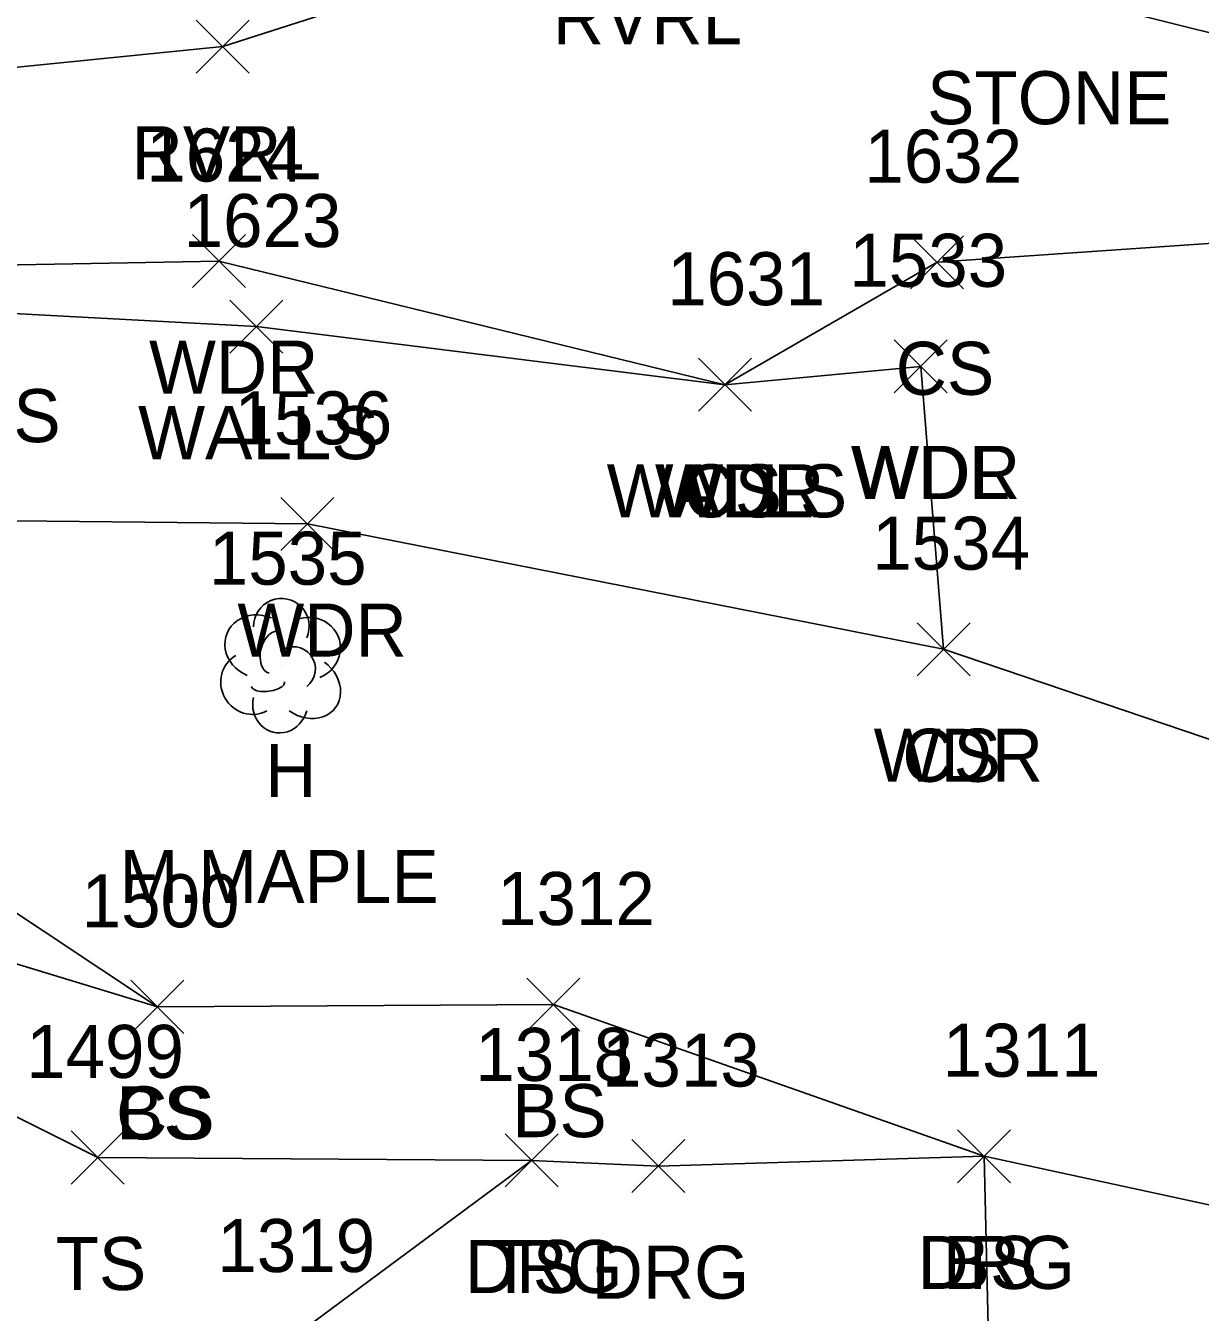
# Model space of a CAD drawing. Extents: x 1537342 to 1542195, y 163002 to 168596.
# Drawn here: x 1541894.54 to 1541938.81, y 163290.52 to 163339.03 of the extents above; entities that cross this region are included whole.
import ezdxf

# ---------------------------------------------------------------- set-up
doc = ezdxf.new("R2010")
doc.units = 0
for name, color, linetype in [('L_A', 7, 'Continuous'), ('L_C', 7, 'Continuous'), ('L_I', 7, 'Continuous'), ('L_TIC', 7, 'Continuous'), ('LASF', 7, 'Continuous'), ('LAWA', 7, 'Continuous'), ('LAWE', 7, 'Continuous'), ('LELB', 7, 'Continuous'), ('LTD', 7, 'Continuous'), ('LWS', 7, 'Continuous'), ('R_A', 7, 'Continuous'), ('R_I', 7, 'Continuous'), ('R_TIC', 7, 'Continuous'), ('RDG', 7, 'Continuous')]:
    doc.layers.add(name, color=color, linetype=linetype)

msp = doc.modelspace()

# ---------------------------------------------------------------- linework, layer by layer
at = {"layer": 'L_TIC'}
for points in [[(1541900.965, 163337.242), (1541902.965, 163339.242)], [(1541902.965, 163337.242), (1541900.965, 163339.242)], [(1541900.823, 163329.154), (1541902.823, 163331.154)], [(1541902.823, 163329.154), (1541900.823, 163331.154)], [(1541927.892, 163329.111), (1541929.892, 163331.111)], [(1541929.892, 163329.111), (1541927.892, 163331.111)], [(1541902.232, 163326.684), (1541904.232, 163328.684)], [(1541904.232, 163326.684), (1541902.232, 163328.684)], [(1541927.278, 163325.185), (1541929.278, 163327.185)], [(1541929.278, 163325.185), (1541927.278, 163327.185)], [(1541927.278, 163325.185), (1541929.278, 163327.185)], [(1541929.278, 163325.185), (1541927.278, 163327.185)], [(1541919.894, 163324.491), (1541921.894, 163326.491)], [(1541921.894, 163324.491), (1541919.894, 163326.491)], [(1541919.894, 163324.491), (1541921.894, 163326.491)], [(1541921.894, 163324.491), (1541919.894, 163326.491)], [(1541919.894, 163324.491), (1541921.894, 163326.491)], [(1541921.894, 163324.491), (1541919.894, 163326.491)], [(1541919.894, 163324.491), (1541921.894, 163326.491)], [(1541921.894, 163324.491), (1541919.894, 163326.491)], [(1541904.155, 163319.242), (1541906.155, 163321.242)], [(1541906.155, 163319.242), (1541904.155, 163321.242)], [(1541928.141, 163314.519), (1541930.141, 163316.519)], [(1541930.141, 163314.519), (1541928.141, 163316.519)], [(1541928.141, 163314.519), (1541930.141, 163316.519)], [(1541930.141, 163314.519), (1541928.141, 163316.519)], [(1541913.432, 163301.118), (1541915.432, 163303.118)], [(1541915.432, 163301.118), (1541913.432, 163303.118)], [(1541898.504, 163301.033), (1541900.504, 163303.033)], [(1541900.504, 163301.033), (1541898.504, 163303.033)], [(1541898.504, 163301.033), (1541900.504, 163303.033)], [(1541900.504, 163301.033), (1541898.504, 163303.033)], [(1541896.255, 163295.352), (1541898.255, 163297.352)], [(1541898.255, 163295.352), (1541896.255, 163297.352)], [(1541929.665, 163295.396), (1541931.665, 163297.396)], [(1541931.665, 163295.396), (1541929.665, 163297.396)], [(1541912.61, 163295.24), (1541914.61, 163297.24)], [(1541914.61, 163295.24), (1541912.61, 163297.24)]]:
    msp.add_lwpolyline(points, dxfattribs=at)
at = {"layer": 'LASF'}
msp.add_lwpolyline([(1541995.881, 163321.623), (1541975.609, 163331.573), (1541964.354, 163336.559), (1541946.913, 163336.834), (1541932.973, 163340.315), (1541930.286, 163345.761)], dxfattribs=at)
at = {"layer": 'LAWA'}
for points in [[(1541928.278, 163326.185), (1541929.141, 163315.519), (1541905.155, 163320.242), (1541889.19, 163320.415), (1541870.486, 163327.732), (1541854.509, 163332.258), (1541871.283, 163331.328), (1541890.104, 163329.934), (1541901.823, 163330.154), (1541920.894, 163325.491)], [(1541928.278, 163326.185), (1541920.894, 163325.491)]]:
    msp.add_lwpolyline(points, dxfattribs=at)
at = {"layer": 'LAWE'}
msp.add_lwpolyline([(1541842.538, 163329.294), (1541847.215, 163332.13), (1541859.961, 163336.541), (1541870.001, 163336.588), (1541887.847, 163336.83), (1541901.965, 163338.242), (1541917.838, 163343.333), (1541930.286, 163345.761), (1541946.347, 163346.77), (1541962.456, 163344.962)], dxfattribs=at)
at = {"layer": 'LELB'}
for points in [[(1541920.894, 163325.491), (1541928.892, 163330.111), (1541946.235, 163331.307), (1541955.972, 163331.056), (1541975.609, 163331.573)], [(1541913.61, 163296.24), (1541897.255, 163296.352), (1541879.102, 163305.411), (1541865.415, 163313.569), (1541849.959, 163321.033), (1541836.165, 163327.361)], [(1541899.504, 163302.033), (1541880.926, 163307.684), (1541867.753, 163316.599), (1541851.251, 163322.573), (1541842.419, 163327.722)], [(1542002.438, 163218.438), (1541992.576, 163218.503), (1541981.665, 163227.078), (1541972.727, 163235.185), (1541952.245, 163252.94), (1541934.224, 163270.875), (1541926.758, 163276.805), (1541931.045, 163280.387), (1541930.665, 163296.396), (1541914.432, 163302.118), (1541899.504, 163302.033), (1541884.497, 163311.998), (1541872.596, 163319.595), (1541857.311, 163324.696)], [(1541972.352, 163296.503), (1541957.804, 163303.546), (1541943.486, 163310.651), (1541929.141, 163315.519)]]:
    msp.add_lwpolyline(points, dxfattribs=at)
at = {"layer": 'LTD'}
msp.add_line((1541904.131, 163314.95), (1541904.131, 163314.95), dxfattribs=at)
msp.add_line((1541904.131, 163314.95), (1541904.131, 163314.95), dxfattribs=at)
msp.add_arc((1541904.178, 163316.384), 1.047, 335.5272, 180.9563, dxfattribs=at)
for centre, major_axis, ratio, start_param, end_param in [((1541903.339, 163315.616), (1.21, -0.512), 0.895232, 1.570796, 4.712389), ((1541905.173, 163315.533), (-1.141, -0.483), 0.949671, 1.570796, 4.712389), ((1541903.923, 163315.408), (-0.208, -0.792), 0.645439, 3.141593, 6.283185), ((1541904.631, 163314.783), (-0.5, 0.667), 0.989748, 3.141593, 6.283185), ((1541903.048, 163314.241), (0.584, -1.042), 0.959034, 3.141593, 6.283185), ((1541905.131, 163314.117), (-1.09, 0.792), 0.841452, 1.570796, 4.712389), ((1541903.673, 163314.2), (-0.625, -0.083), 0.423636, 0, 3.141593), ((1541904.131, 163313.45), (0.265, 1.061), 0.942809, 1.570796, 4.712389)]:
    msp.add_ellipse(centre, major_axis=major_axis, ratio=ratio, start_param=start_param, end_param=end_param, dxfattribs=at)
at = {"layer": 'LWS'}
msp.add_lwpolyline([(1541857.311, 163324.696), (1541870.486, 163327.732), (1541886.38, 163327.11), (1541891.246, 163328.326), (1541903.232, 163327.684), (1541920.894, 163325.491)], dxfattribs=at)
at = {"layer": 'R_TIC'}
for points in [[(1541929.665, 163295.396), (1541931.665, 163297.396)], [(1541931.665, 163295.396), (1541929.665, 163297.396)], [(1541912.61, 163295.24), (1541914.61, 163297.24)], [(1541914.61, 163295.24), (1541912.61, 163297.24)], [(1541917.384, 163295.027), (1541919.384, 163297.027)], [(1541919.384, 163295.027), (1541917.384, 163297.027)]]:
    msp.add_lwpolyline(points, dxfattribs=at)
at = {"layer": 'RDG'}
msp.add_lwpolyline([(1542017.62, 163206.917), (1542015.196, 163226.11), (1542009.877, 163243.692), (1541994.503, 163258.921), (1541988.515, 163265.136), (1541982.386, 163272.123), (1541977.907, 163278.251), (1541973.34, 163281.582), (1541963.148, 163285.487), (1541948.659, 163292.511), (1541930.665, 163296.396), (1541918.384, 163296.027), (1541913.61, 163296.24), (1541903.895, 163289.032)], dxfattribs=at)

# ---------------------------------------------------------------- texts
at = {"layer": 'L_A'}
for s, p in [('RVRL', (1541914.405, 163338.333)), ('STONE', (1541928.516, 163335.315)), ('RVRL', (1541898.532, 163333.242)), ('WDR', (1541899.185, 163325.154)), ('CS', (1541927.333, 163325.111)), ('WALLS', (1541886.789, 163323.326)), ('WALLS', (1541898.776, 163322.684)), ('WDR', (1541925.641, 163321.185)), ('WDL', (1541925.696, 163321.185)), ('WALLS', (1541916.437, 163320.491)), ('CS', (1541919.335, 163320.491)), ('WDR', (1541918.256, 163320.491)), ('WDL', (1541918.311, 163320.491)), ('WDR', (1541902.517, 163315.242)), ('WDR', (1541926.503, 163310.519)), ('CS', (1541927.582, 163310.519)), ('H', (1541903.564, 163309.95)), ('CS', (1541897.945, 163297.033)), ('BS', (1541897.945, 163297.033)), ('BS', (1541912.873, 163297.118)), ('BS', (1541929.106, 163291.396)), ('TS', (1541895.664, 163291.352)), ('TS', (1541912.02, 163291.24))]:
    msp.add_text(s, height=2, dxfattribs=at).set_placement(p)
at = {"layer": 'L_C'}
msp.add_text('M.MAPLE', height=2, dxfattribs=at).set_placement((1541898.068, 163305.95))
at = {"layer": 'L_I'}
for s, p in [('1624', (1541899.083, 163333.154)), ('1632', (1541926.152, 163333.111)), ('1623', (1541900.492, 163330.684)), ('1533', (1541925.586, 163329.185)), ('1533', (1541925.586, 163329.185)), ('1631', (1541918.721, 163328.491)), ('1631', (1541918.721, 163328.491)), ('1631', (1541918.721, 163328.491)), ('1631', (1541918.721, 163328.491)), ('1536', (1541902.407, 163323.242)), ('1534', (1541926.448, 163318.519)), ('1534', (1541926.448, 163318.519)), ('1535', (1541901.439, 163317.95)), ('1500', (1541896.646, 163305.033)), ('1500', (1541896.646, 163305.033)), ('1312', (1541912.306, 163305.118)), ('1499', (1541894.554, 163299.352)), ('1318', (1541911.485, 163299.24)), ('1311', (1541929.107, 163299.396))]:
    msp.add_text(s, height=2, dxfattribs=at).set_placement(p)
at = {"layer": 'R_A'}
for p in [(1541928.154, 163291.396), (1541911.098, 163291.24), (1541915.872, 163291.027)]:
    msp.add_text('DRG', height=2, dxfattribs=at).set_placement(p)
at = {"layer": 'R_I'}
for s, p in [('1318', (1541911.485, 163299.24)), ('1311', (1541929.107, 163299.396)), ('1313', (1541916.259, 163299.027)), ('1319', (1541901.762, 163292.032)), ('1319', (1541901.762, 163292.032))]:
    msp.add_text(s, height=2, dxfattribs=at).set_placement(p)

doc.saveas('drawing.dxf')
